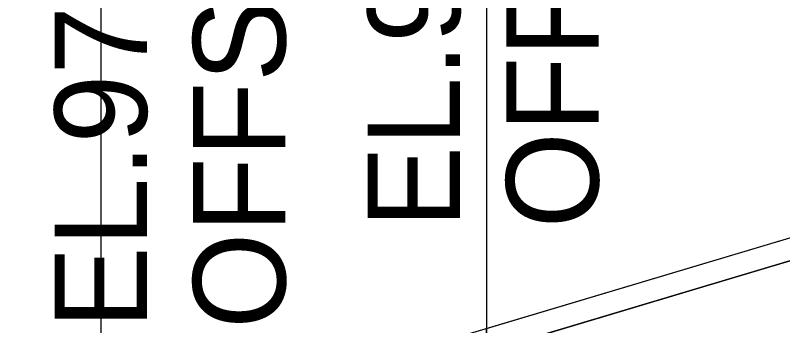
# Model space of a CAD drawing. Extents: x -120 to 2876, y -25 to 8560.
# Drawn here: x 1495.04 to 1503.35, y 1001.56 to 1004.92 of the extents above; entities that cross this region are included whole.
import ezdxf

# ---------------------------------------------------------------- set-up
doc = ezdxf.new("R2010")
doc.units = 0
for name, color, linetype in [('DESIGN - EARTHWORK - Excavation Limit Lines', 7, 'Continuous'), ('DESIGN - EARTHWORK - Shapes', 7, 'Continuous'), ('DESIGN - TYPICAL - Slope Tie Text', 7, 'Continuous'), ('SURVEY - GROUND - Bottom of Topsoil Layer', 7, 'Continuous'), ('SURVEY - GROUND - Top of Ground', 7, 'Continuous')]:
    doc.layers.add(name, color=color, linetype=linetype)

msp = doc.modelspace()

# ---------------------------------------------------------------- linework, layer by layer
at = {"layer": 'DESIGN - EARTHWORK - Excavation Limit Lines'}
for p, q in [((1495.9652, 1027.022), (1495.9652, 974.522)), ((1500.14, 1024.9694), (1500.14, 972.4694))]:
    msp.add_line(p, q, dxfattribs=at)
at = {"layer": 'DESIGN - EARTHWORK - Shapes'}
for points in [[(1500.14, 1001.5269), (1503.7366, 1002.6026), (1508.5781, 1002.9497), (1507.9944, 1002.6578), (1503.7366, 1002.3526), (1500.14, 1001.2769)], [(1500.14, 1001.2769), (1503.7366, 1002.3526), (1507.9944, 1002.6578), (1504.5227, 1000.922), (1502.64, 999.9806), (1500.14, 999.9806)]]:
    msp.add_lwpolyline(points, close=True, dxfattribs=at)
at = {"layer": 'SURVEY - GROUND - Bottom of Topsoil Layer'}
msp.add_line((1499.4032, 1001.0566), (1503.7366, 1002.3526), dxfattribs=at)
at = {"layer": 'SURVEY - GROUND - Top of Ground'}
msp.add_lwpolyline([(1474.6982, 1001.819), (1479.8369, 1003.7615), (1482.7947, 1003.0458), (1485.7724, 1001.4949), (1490.3061, 1001.1529), (1491.0391, 1000.925), (1494.0601, 1000.8733), (1496.2559, 1000.7566), (1499.4032, 1001.3066), (1503.7366, 1002.6026), (1518.0699, 1003.6301)], dxfattribs=at)

# ---------------------------------------------------------------- texts
at = {"layer": 'DESIGN - TYPICAL - Slope Tie Text'}
for s, p in [('OFFSET 50.14', (1501.3541, 1002.6103)), ('OFFSET 45.97', (1497.9652, 1001.522)), ('EL.977.98', (1499.8541, 1002.6103)), ('EL.978.77', (1496.4652, 1001.522))]:
    msp.add_text(s, height=1, rotation=90, dxfattribs=at).set_placement(p)

doc.saveas('drawing.dxf')
